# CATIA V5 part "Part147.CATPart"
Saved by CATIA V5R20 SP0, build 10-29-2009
Part number: FA 105700-1
Revision: ANY
Definition: UNKNOWN
Nomenclature: FA 105700-1
Source: Unknown
Bounding box of the stored display mesh (mm): x -2.853 to 2.853, y 0.2 to 2.5, z -3 to 3
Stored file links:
  C:\Users\Utente\Desktop\IO LAVORO\3D X SITO CF\CUMSA\3D files FA\FA 105706-20\Part147.CATPart

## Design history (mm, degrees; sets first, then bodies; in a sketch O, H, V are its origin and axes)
Body1 "Cortar-Extruir1" (main body)
  Solid1: solid without history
